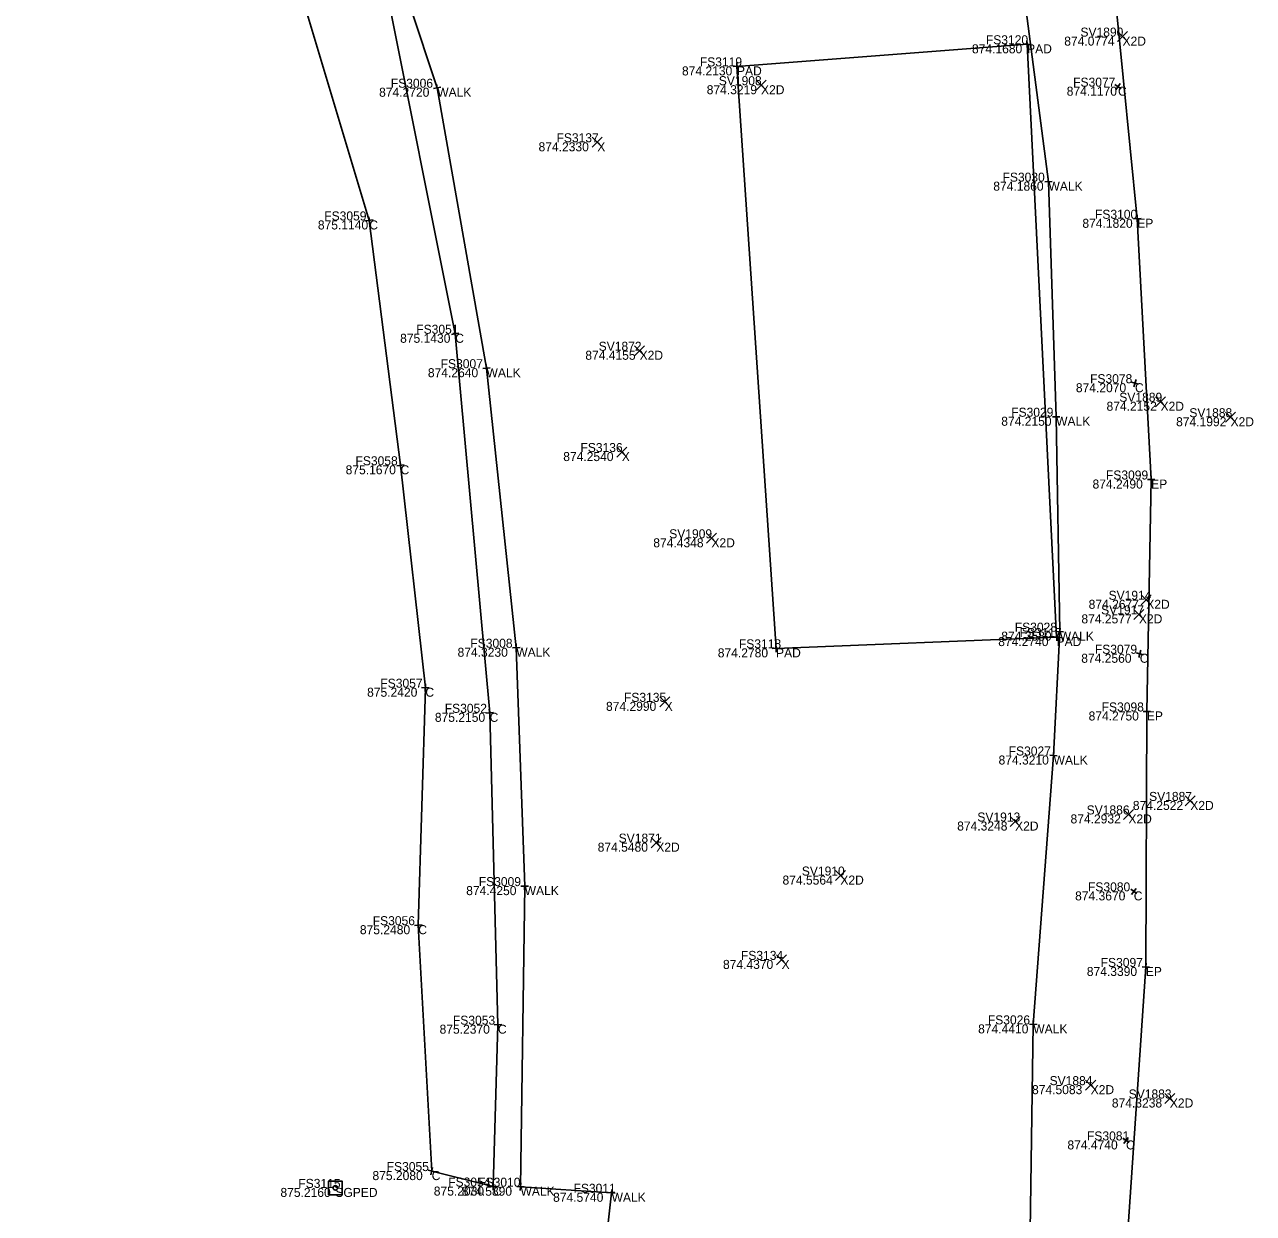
# Model space of a CAD drawing. Extents: x 1479481 to 1575806, y 316056 to 379927.
# Drawn here: x 1480136.78 to 1480144.96, y 379408.84 to 379416.75 of the extents above; entities that cross this region are included whole.
import ezdxf

# ---------------------------------------------------------------- set-up
doc = ezdxf.new("R2010")
doc.units = 0
for name, color, linetype in [('PV_X_Curb', 7, 'Continuous'), ('PV_X_Walk', 7, 'Continuous'), ('RD_X_Concrete_Pad', 7, 'Continuous'), ('SG_X_Poles', 7, 'Continuous'), ('SV_X_Random_Point', 7, 'Continuous'), ('SV_X_Shot_Marker', 7, 'Continuous'), ('SV_X_Text_Comment', 7, 'Continuous'), ('SV_X_Text_Elevation', 7, 'Continuous'), ('SV_X_Text_Name', 7, 'Continuous')]:
    doc.layers.add(name, color=color, linetype=linetype)

msp = doc.modelspace()

# ---------------------------------------------------------------- linework, layer by layer
at = {"layer": 'PV_X_Curb'}
for points in [[(1480144.119, 379408.6925), (1480144.24, 379410.484), (1480144.247, 379412.184), (1480144.2756, 379413.7273), (1480144.183, 379415.462), (1480143.996, 379417.344), (1480143.813, 379419.16), (1480143.496, 379420.71), (1480143.015, 379422.278), (1480142.354, 379423.817), (1480141.636, 379425.054), (1480140.711, 379426.236), (1480139.646, 379427.551), (1480138.485, 379428.822), (1480137.236, 379430.074), (1480137.133, 379430.2922), (1480135.667, 379431.559), (1480135.19, 379432.3319), (1480118.45, 379448.1601)], [(1480143.467, 379408.427), (1480143.491, 379410.102), (1480143.626, 379411.891), (1480143.667, 379412.715), (1480143.643, 379414.145), (1480143.592, 379415.709), (1480143.406, 379417.136), (1480143.175, 379418.964), (1480142.832, 379420.583), (1480142.491, 379421.692), (1480141.812, 379423.272), (1480140.724, 379425.16), (1480139.421, 379426.804), (1480138.202, 379428.161), (1480136.669, 379429.706), (1480137.1142, 379430.0955), (1480136.349, 379430.778), (1480135, 379431.8972), (1480118.039, 379447.9143)], [(1480132.735, 379425.624), (1480133.489, 379424.793), (1480135.438, 379422.771), (1480136.612, 379421.448), (1480137.609, 379420.095), (1480138.484, 379418.724), (1480139.167, 379417.086), (1480139.644, 379414.697), (1480139.873, 379412.175), (1480139.928, 379410.1), (1480139.896, 379409.023), (1480139.487, 379409.126), (1480139.398, 379410.762), (1480139.445, 379412.342), (1480139.28, 379413.822), (1480139.072, 379415.451), (1480138.646, 379416.869), (1480138.065, 379418.417), (1480137.434, 379419.594), (1480136.416, 379420.968), (1480135.065, 379422.458), (1480133.739, 379423.908), (1480132.463, 379425.289)]]:
    msp.add_lwpolyline(points, dxfattribs=at)
at = {"layer": 'PV_X_Walk'}
for points in [[(1480121.511, 379381.7697), (1480134.604, 379395.5795), (1480136.695, 379398.1481), (1480138.804, 379401.064), (1480139.196, 379402.304), (1480139.794, 379404.164), (1480140.245, 379405.64), (1480140.457, 379406.671), (1480140.54, 379407.685), (1480140.6844, 379408.9816), (1480140.078, 379409.022), (1480140.106, 379411.022), (1480140.05, 379412.608), (1480139.852, 379414.468), (1480139.524, 379416.334), (1480139.163, 379417.424), (1480138.324, 379419.293), (1480136.856, 379421.479), (1480135.693, 379422.823), (1480134.581, 379423.922), (1480132.876, 379425.614), (1480132.82, 379425.698), (1480131.146, 379427.408), (1480114.834, 379442.9595)], [(1480143.467, 379408.427), (1480143.491, 379410.102), (1480143.626, 379411.891), (1480143.667, 379412.715), (1480143.643, 379414.145), (1480143.592, 379415.709), (1480143.406, 379417.136), (1480143.175, 379418.964), (1480142.832, 379420.583), (1480142.491, 379421.692), (1480141.812, 379423.272), (1480140.724, 379425.16), (1480139.421, 379426.804), (1480138.202, 379428.161), (1480136.669, 379429.706), (1480135.545, 379428.421), (1480134.397, 379429.433)], [(1480132.876, 379425.614), (1480134.581, 379423.922), (1480135.693, 379422.823), (1480136.856, 379421.479), (1480138.324, 379419.293), (1480139.163, 379417.424), (1480139.524, 379416.334), (1480139.852, 379414.468), (1480140.05, 379412.608), (1480140.106, 379411.022), (1480140.078, 379409.022), (1480140.6844, 379408.9816), (1480140.54, 379407.685)]]:
    msp.add_lwpolyline(points, dxfattribs=at)
at = {"layer": 'RD_X_Concrete_Pad'}
msp.add_lwpolyline([(1480143.646, 379412.679), (1480141.779, 379412.604), (1480141.519, 379416.476), (1480143.45, 379416.623)], close=True, dxfattribs=at)
at = {"layer": 'SG_X_Poles'}
msp.add_lwpolyline([(1480138.801, 379408.969), (1480138.891, 379408.969), (1480138.891, 379409.059), (1480138.801, 379409.059)], close=True, dxfattribs=at)
msp.add_circle((1480138.846, 379409.014), 0.015, dxfattribs=at)
at = {"layer": 'SV_X_Random_Point'}
for p, q in [((1480144.0517, 379416.6407), (1480144.1183, 379416.7075)), ((1480144.0517, 379416.7075), (1480144.1183, 379416.6407)), ((1480141.6457, 379416.3173), (1480141.7123, 379416.3841)), ((1480141.6457, 379416.3841), (1480141.7123, 379416.3173)), ((1480140.5557, 379415.9376), (1480140.6223, 379416.0044)), ((1480140.5557, 379416.0044), (1480140.6223, 379415.9376)), ((1480140.8377, 379414.5506), (1480140.9043, 379414.6174)), ((1480140.8377, 379414.6174), (1480140.9043, 379414.5506)), ((1480144.3047, 379414.2114), (1480144.3713, 379414.2782)), ((1480144.3047, 379414.2782), (1480144.3713, 379414.2114)), ((1480144.7707, 379414.1083), (1480144.8373, 379414.1751)), ((1480144.7707, 379414.1751), (1480144.8373, 379414.1083)), ((1480140.7187, 379413.8766), (1480140.7853, 379413.9434)), ((1480140.7187, 379413.9434), (1480140.7853, 379413.8766)), ((1480141.3157, 379413.3029), (1480141.3823, 379413.3697)), ((1480141.3157, 379413.3697), (1480141.3823, 379413.3029)), ((1480144.2097, 379412.8937), (1480144.2763, 379412.9605)), ((1480144.2097, 379412.9605), (1480144.2763, 379412.8937)), ((1480144.1607, 379412.7965), (1480144.2273, 379412.8633)), ((1480144.1607, 379412.8633), (1480144.2273, 379412.7965)), ((1480141.0047, 379412.2146), (1480141.0713, 379412.2814)), ((1480141.0047, 379412.2814), (1480141.0713, 379412.2146)), ((1480144.5027, 379411.5554), (1480144.5693, 379411.6222)), ((1480144.5027, 379411.6222), (1480144.5693, 379411.5554)), ((1480144.0907, 379411.4656), (1480144.1573, 379411.5324)), ((1480144.0907, 379411.5324), (1480144.1573, 379411.4656)), ((1480143.3367, 379411.4184), (1480143.4033, 379411.4852)), ((1480143.3367, 379411.4852), (1480143.4033, 379411.4184)), ((1480140.9487, 379411.2778), (1480141.0153, 379411.3446)), ((1480140.9487, 379411.3446), (1480141.0153, 379411.2778)), ((1480142.1737, 379411.0588), (1480142.2403, 379411.1256)), ((1480142.1737, 379411.1256), (1480142.2403, 379411.0588)), ((1480141.7827, 379410.4976), (1480141.8493, 379410.5644)), ((1480141.7827, 379410.5644), (1480141.8493, 379410.4976)), ((1480143.8397, 379409.6643), (1480143.9063, 379409.7311)), ((1480143.8397, 379409.7311), (1480143.9063, 379409.6643)), ((1480144.3667, 379409.5756), (1480144.4333, 379409.6424)), ((1480144.3667, 379409.6424), (1480144.4333, 379409.5756))]:
    msp.add_line(p, q, dxfattribs=at)
at = {"layer": 'SV_X_Shot_Marker'}
for p, q in [((1480143.4481, 379416.6479), (1480143.4519, 379416.5981)), ((1480143.4251, 379416.6211), (1480143.4749, 379416.6249)), ((1480143.45, 379416.623), (1480143.45, 379416.623)), ((1480141.5207, 379416.4511), (1480141.5173, 379416.501)), ((1480141.4941, 379416.4743), (1480141.5439, 379416.4777)), ((1480141.519, 379416.476), (1480141.519, 379416.476)), ((1480139.4994, 379416.3297), (1480139.5486, 379416.3383)), ((1480139.5283, 379416.3094), (1480139.5197, 379416.3586)), ((1480139.524, 379416.334), (1480139.524, 379416.334)), ((1480144.0348, 379416.3558), (1480144.0752, 379416.3262)), ((1480144.0402, 379416.3208), (1480144.0698, 379416.3612)), ((1480144.055, 379416.341), (1480144.055, 379416.341)), ((1480143.567, 379415.7082), (1480143.617, 379415.7098)), ((1480143.5928, 379415.684), (1480143.5912, 379415.734)), ((1480143.592, 379415.709), (1480143.592, 379415.709)), ((1480139.0472, 379415.4478), (1480139.0968, 379415.4542)), ((1480139.0752, 379415.4262), (1480139.0688, 379415.4758)), ((1480139.072, 379415.451), (1480139.072, 379415.451)), ((1480144.158, 379415.4607), (1480144.208, 379415.4633)), ((1480144.1843, 379415.437), (1480144.1817, 379415.487)), ((1480144.183, 379415.462), (1480144.183, 379415.462)), ((1480139.6685, 379414.7019), (1480139.6195, 379414.6921)), ((1480139.6391, 379414.7215), (1480139.6489, 379414.6725)), ((1480139.644, 379414.697), (1480139.644, 379414.697)), ((1480139.8271, 379414.4654), (1480139.8769, 379414.4707)), ((1480139.8546, 379414.4432), (1480139.8494, 379414.4929)), ((1480139.852, 379414.468), (1480139.852, 379414.468)), ((1480144.1441, 379414.3753), (1480144.1919, 379414.3608)), ((1480144.1607, 379414.3441), (1480144.1753, 379414.3919)), ((1480144.168, 379414.368), (1480144.168, 379414.368)), ((1480143.618, 379414.1446), (1480143.668, 379414.1454)), ((1480143.6434, 379414.12), (1480143.6426, 379414.17)), ((1480143.643, 379414.145), (1480143.643, 379414.145)), ((1480139.2552, 379413.8192), (1480139.3048, 379413.8248)), ((1480139.2828, 379413.7972), (1480139.2772, 379413.8469)), ((1480139.28, 379413.822), (1480139.28, 379413.822)), ((1480144.2506, 379413.7277), (1480144.3006, 379413.7268)), ((1480144.2751, 379413.7023), (1480144.276, 379413.7523)), ((1480144.2756, 379413.7273), (1480144.2756, 379413.7273)), ((1480143.6658, 379412.69), (1480143.6682, 379412.74)), ((1480143.671, 379412.68), (1480143.621, 379412.678)), ((1480143.642, 379412.7163), (1480143.692, 379412.7138)), ((1480143.647, 379412.654), (1480143.645, 379412.704)), ((1480143.646, 379412.679), (1480143.646, 379412.679)), ((1480143.667, 379412.715), (1480143.667, 379412.715)), ((1480140.025, 379412.6071), (1480140.075, 379412.6089)), ((1480140.0509, 379412.583), (1480140.0491, 379412.633)), ((1480140.05, 379412.608), (1480140.05, 379412.608)), ((1480141.804, 379412.605), (1480141.754, 379412.603)), ((1480141.78, 379412.579), (1480141.778, 379412.629)), ((1480141.779, 379412.604), (1480141.779, 379412.604)), ((1480144.1759, 379412.5747), (1480144.2241, 379412.5614)), ((1480144.2066, 379412.5921), (1480144.1934, 379412.5439)), ((1480144.2, 379412.568), (1480144.2, 379412.568)), ((1480139.42, 379412.3428), (1480139.47, 379412.3413)), ((1480139.4443, 379412.317), (1480139.4457, 379412.367)), ((1480139.445, 379412.342), (1480139.445, 379412.342)), ((1480139.8979, 379412.1773), (1480139.8481, 379412.1728)), ((1480139.8707, 379412.1999), (1480139.8753, 379412.1501)), ((1480139.873, 379412.175), (1480139.873, 379412.175)), ((1480144.222, 379412.1841), (1480144.272, 379412.1839)), ((1480144.2469, 379412.159), (1480144.2471, 379412.209)), ((1480144.247, 379412.184), (1480144.247, 379412.184)), ((1480143.6241, 379411.8661), (1480143.6279, 379411.9159)), ((1480143.6011, 379411.8929), (1480143.6509, 379411.8891)), ((1480143.626, 379411.891), (1480143.626, 379411.891)), ((1480140.081, 379411.0224), (1480140.131, 379411.0217)), ((1480140.1057, 379410.997), (1480140.1064, 379411.047)), ((1480140.106, 379411.022), (1480140.106, 379411.022)), ((1480144.1401, 379411.0021), (1480144.1799, 379410.9719)), ((1480144.1449, 379410.9671), (1480144.1751, 379411.007)), ((1480144.16, 379410.987), (1480144.16, 379410.987)), ((1480139.373, 379410.7607), (1480139.423, 379410.7634)), ((1480139.3994, 379410.737), (1480139.3966, 379410.787)), ((1480139.398, 379410.762), (1480139.398, 379410.762)), ((1480144.2383, 379410.4591), (1480144.2417, 379410.509)), ((1480144.2151, 379410.4857), (1480144.2649, 379410.4823)), ((1480144.24, 379410.484), (1480144.24, 379410.484)), ((1480139.953, 379410.1007), (1480139.903, 379410.0993)), ((1480139.9273, 379410.125), (1480139.9287, 379410.075)), ((1480139.928, 379410.1), (1480139.928, 379410.1)), ((1480143.466, 379410.1024), (1480143.516, 379410.1017)), ((1480143.4906, 379410.077), (1480143.4914, 379410.127)), ((1480143.491, 379410.102), (1480143.491, 379410.102)), ((1480144.0876, 379409.3445), (1480144.1284, 379409.3155)), ((1480144.0935, 379409.3096), (1480144.1225, 379409.3504)), ((1480144.108, 379409.33), (1480144.108, 379409.33)), ((1480139.5112, 379409.1199), (1480139.4628, 379409.1321)), ((1480139.4809, 379409.1018), (1480139.4931, 379409.1503)), ((1480139.487, 379409.126), (1480139.487, 379409.126)), ((1480139.8967, 379409.048), (1480139.8953, 379408.998)), ((1480140.0763, 379408.9971), (1480140.0797, 379409.047)), ((1480139.921, 379409.0223), (1480139.871, 379409.0238)), ((1480139.896, 379409.023), (1480139.896, 379409.023)), ((1480140.1029, 379409.0204), (1480140.0531, 379409.0237)), ((1480140.078, 379409.022), (1480140.078, 379409.022)), ((1480140.6596, 379408.9844), (1480140.7093, 379408.9789)), ((1480140.6817, 379408.9568), (1480140.6872, 379409.0065)), ((1480140.6844, 379408.9816), (1480140.6844, 379408.9816))]:
    msp.add_line(p, q, dxfattribs=at)

# ---------------------------------------------------------------- texts
at = {"layer": 'SV_X_Text_Comment'}
for s, p in [('X2D', (1480144.085, 379416.6141)), ('PAD', (1480143.45, 379416.563)), ('PAD', (1480141.519, 379416.416)), ('WALK', (1480139.524, 379416.274)), ('X2D', (1480141.679, 379416.2907)), ('C', (1480144.055, 379416.281)), ('X', (1480140.589, 379415.911)), ('WALK', (1480143.592, 379415.649)), ('C', (1480139.072, 379415.391)), ('EP', (1480144.183, 379415.402)), ('C', (1480139.644, 379414.637)), ('X2D', (1480140.871, 379414.524)), ('WALK', (1480139.852, 379414.408)), ('C', (1480144.168, 379414.308)), ('X2D', (1480144.338, 379414.1848)), ('WALK', (1480143.643, 379414.085)), ('X2D', (1480144.804, 379414.0817)), ('X', (1480140.752, 379413.85)), ('C', (1480139.28, 379413.762)), ('EP', (1480144.2756, 379413.6673)), ('X2D', (1480141.349, 379413.2763)), ('X2D', (1480144.243, 379412.8671)), ('X2D', (1480144.194, 379412.7699)), ('PAD', (1480143.646, 379412.619)), ('WALK', (1480143.667, 379412.655)), ('WALK', (1480140.05, 379412.548)), ('PAD', (1480141.779, 379412.544)), ('C', (1480144.2, 379412.508)), ('C', (1480139.445, 379412.282)), ('X', (1480141.038, 379412.188)), ('C', (1480139.873, 379412.115)), ('EP', (1480144.247, 379412.124)), ('WALK', (1480143.626, 379411.831)), ('X2D', (1480144.536, 379411.5288)), ('X2D', (1480144.124, 379411.439)), ('X2D', (1480143.37, 379411.3918)), ('X2D', (1480140.982, 379411.2512)), ('X2D', (1480142.207, 379411.0322)), ('WALK', (1480140.106, 379410.962)), ('C', (1480144.16, 379410.927)), ('C', (1480139.398, 379410.702)), ('X', (1480141.816, 379410.471)), ('EP', (1480144.24, 379410.424)), ('C', (1480139.928, 379410.04)), ('WALK', (1480143.491, 379410.042)), ('X2D', (1480143.873, 379409.6377)), ('X2D', (1480144.4, 379409.549)), ('C', (1480144.108, 379409.27)), ('C', (1480139.487, 379409.066)), ('SGPED', (1480138.846, 379408.954)), ('C', (1480139.896, 379408.963)), ('WALK', (1480140.078, 379408.962)), ('WALK', (1480140.6844, 379408.9216))]:
    msp.add_text(s, height=0.06, dxfattribs=at).set_placement(p)
at = {"layer": 'SV_X_Text_Elevation'}
for s, p in [('874.0774', (1480143.6972, 379416.6141)), ('874.1680', (1480143.083, 379416.563)), ('874.2130', (1480141.1529, 379416.416)), ('874.2720', (1480139.1371, 379416.274)), ('874.3219', (1480141.3176, 379416.2907)), ('874.1170', (1480143.7135, 379416.281)), ('874.2330', (1480140.1983, 379415.911)), ('874.1860', (1480143.225, 379415.649)), ('875.1140', (1480138.7296, 379415.391)), ('874.1820', (1480143.8179, 379415.402)), ('875.1430', (1480139.277, 379414.637)), ('874.4155', (1480140.5096, 379414.524)), ('874.2640', (1480139.4618, 379414.408)), ('874.2070', (1480143.7745, 379414.308)), ('874.2152', (1480143.9785, 379414.1848)), ('874.2150', (1480143.2779, 379414.085)), ('874.1992', (1480144.4417, 379414.0817)), ('874.2540', (1480140.3627, 379413.85)), ('875.1670', (1480138.9144, 379413.762)), ('874.2490', (1480143.8854, 379413.6673)), ('874.4348', (1480140.9621, 379413.2763)), ('874.2677', (1480143.8594, 379412.8671)), ('874.2577', (1480143.8114, 379412.7699)), ('874.2740', (1480143.2577, 379412.619)), ('874.2580', (1480143.2782, 379412.655)), ('874.3230', (1480139.6593, 379412.548)), ('874.2780', (1480141.3912, 379412.544)), ('874.2560', (1480143.8103, 379412.508)), ('875.2420', (1480139.0572, 379412.282)), ('874.2990', (1480140.6473, 379412.188)), ('875.2150', (1480139.5083, 379412.115)), ('874.2750', (1480143.8592, 379412.124)), ('874.3210', (1480143.2599, 379411.831)), ('874.2522', (1480144.1538, 379411.5288)), ('874.2932', (1480143.739, 379411.439)), ('874.3248', (1480142.9845, 379411.3918)), ('874.5480', (1480140.5918, 379411.2512)), ('874.5564', (1480141.822, 379411.0322)), ('874.4250', (1480139.7167, 379410.962)), ('874.3670', (1480143.7693, 379410.927)), ('875.2480', (1480139.0092, 379410.702)), ('874.4370', (1480141.4258, 379410.471)), ('874.3390', (1480143.8474, 379410.424)), ('875.2370', (1480139.5397, 379410.04)), ('874.4410', (1480143.124, 379410.042)), ('874.5083', (1480143.4828, 379409.6377)), ('874.3238', (1480144.014, 379409.549)), ('874.4740', (1480143.7183, 379409.27)), ('875.2080', (1480139.093, 379409.066)), ('875.2160', (1480138.4804, 379408.954)), ('875.2030', (1480139.5011, 379408.963)), ('874.5890', (1480139.6873, 379408.962)), ('874.5740', (1480140.2952, 379408.9216))]:
    msp.add_text(s, height=0.06, dxfattribs=at).set_placement(p)
at = {"layer": 'SV_X_Text_Name'}
for s, p in [('SV1890', (1480143.8049, 379416.6741)), ('FS3120', (1480143.1756, 379416.623)), ('FS3119', (1480141.272, 379416.476)), ('SV1908', (1480141.3979, 379416.3507)), ('FS3077', (1480143.7564, 379416.341)), ('FS3006', (1480139.2151, 379416.334)), ('FS3137', (1480140.3179, 379415.971)), ('FS3030', (1480143.2864, 379415.709)), ('FS3059', (1480138.772, 379415.451)), ('FS3100', (1480143.9019, 379415.462)), ('FS3051', (1480139.3845, 379414.697)), ('SV1872', (1480140.5985, 379414.584)), ('FS3007', (1480139.5468, 379414.468)), ('FS3078', (1480143.869, 379414.368)), ('SV1889', (1480144.0636, 379414.2448)), ('FS3029', (1480143.344, 379414.145)), ('SV1888', (1480144.5296, 379414.1417)), ('FS3136', (1480140.4771, 379413.91)), ('FS3058', (1480138.98, 379413.822)), ('FS3099', (1480143.9746, 379413.7273)), ('SV1909', (1480141.0679, 379413.3363)), ('SV1914', (1480143.9922, 379412.9271)), ('SV1917', (1480143.9427, 379412.8299)), ('FS3028', (1480143.368, 379412.715)), ('FS3117', (1480143.3995, 379412.679)), ('FS3008', (1480139.7444, 379412.608)), ('FS3118', (1480141.532, 379412.604)), ('FS3079', (1480143.901, 379412.568)), ('FS3057', (1480139.1455, 379412.342)), ('FS3135', (1480140.7669, 379412.248)), ('FS3052', (1480139.574, 379412.175)), ('FS3098', (1480143.9461, 379412.184)), ('FS3027', (1480143.3274, 379411.891)), ('SV1887', (1480144.262, 379411.5888)), ('SV1913', (1480143.1187, 379411.4518)), ('SV1886', (1480143.8463, 379411.499)), ('SV1871', (1480140.7315, 379411.3112)), ('FS3009', (1480139.8004, 379411.022)), ('SV1910', (1480141.9505, 379411.0922)), ('FS3080', (1480143.8553, 379410.987)), ('FS3056', (1480139.0947, 379410.762)), ('FS3134', (1480141.5453, 379410.531)), ('FS3097', (1480143.9396, 379410.484)), ('FS3053', (1480139.6285, 379410.1)), ('FS3026', (1480143.1887, 379410.102)), ('SV1884', (1480143.5995, 379409.6977)), ('SV1883', (1480144.126, 379409.609)), ('FS3081', (1480143.8485, 379409.33)), ('FS3055', (1480139.1875, 379409.126)), ('FS3115', (1480138.5995, 379409.014)), ('FS3054', (1480139.597, 379409.023)), ('FS3010', (1480139.7969, 379409.022)), ('FS3011', (1480140.4311, 379408.9816))]:
    msp.add_text(s, height=0.06, dxfattribs=at).set_placement(p)

doc.saveas('drawing.dxf')
